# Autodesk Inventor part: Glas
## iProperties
Created: 2005-01
Part Number: Glas
Document SubType Name: Modeling
Designer: KK
Manufacturer: Standard
Standards Organization: Custom
Description: GLAS ELIPSE
Author: KK
Title: GLAS ELIPSE
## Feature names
1. Extrusion1
2. Fase2 [Chamfer]
3. Sweeping1
